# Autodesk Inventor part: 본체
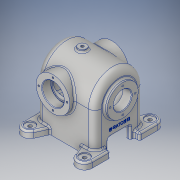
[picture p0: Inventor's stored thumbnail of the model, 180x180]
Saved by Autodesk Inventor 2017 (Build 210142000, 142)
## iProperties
Part Number: 본체
Material: 알루미늄 6061
Document SubType Name: Modeling
Designer: MRC
Density: 2.7 g/cm^3
Appearance: 알루미늄 - 평지
Mass: 1383.94 g
Surface Area: 1150.22 cm^2
Volume: 512.571 cm^3
Author: MRC
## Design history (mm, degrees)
sketch "스케치2"
  geometry: C1 r 45 at (0, 0); 1 further point
  constraints: 1 centre point, 1 coincident
  dimensions: "d0" = 90 diameter of C1
extrude "돌출1" new body sketch "스케치2" distance "d1" = 68; taper "d3" = 0 deg; dims "d2" = 40, "d4" = 0
sketch "스케치3"
  geometry: C1 r 28.5 at (0, 0); 1 further point
  constraints: 1 centre point, 1 coincident
  dimensions: "d5" = 57 diameter of C1
extrude "돌출2" join sketch "스케치3" distance "d6" = 6; taper "d7" = 0 deg
fillet "모깎기1" dims "d8" = 12
sketch "스케치4"
  geometry: C1 r 16.5 at (0, 0); 1 further point
  constraints: 1 centre point, 1 coincident
  dimensions: "d9" = 33 diameter of C1
extrude "돌출3" cut sketch "스케치4" distance "d10" = 16; taper "d11" = 0 deg
sketch "스케치5"
  geometry: C1 r 36 at (0, 0); 1 further point
  constraints: 1 centre point, 1 coincident
  dimensions: "d12" = 72 diameter of C1
extrude "돌출4" cut sketch "스케치5" distance "d13" = 90; taper "d14" = 0 deg
node "작업 평면1"
sketch "스케치11"
  geometry: L1 (28, -45)-(-56, -45); L2 (-68, -33)-(-68, 33); L3 (-56, 45)-(28, 45); L4 (40, 33)-(40, -33); L5 (-56, -36)-(28, -36); L6 (31, -33)-(31, 33); L7 (28, 36)-(-56, 36); L8 (-59, 33)-(-59, -33); A1 r 12 centre (28, -33) between (28, -45) and (40, -33); A2 r 12 centre (-56, -33) between (-68, -33) and (-56, -45); A3 r 12 centre (-56, 33) between (-56, 45) and (-68, 33); A4 r 12 centre (28, 33) between (40, 33) and (28, 45); A5 r 3 centre (28, -33) between (28, -36) and (31, -33); A6 r 3 centre (28, 33) between (31, 33) and (28, 36); A7 r 3 centre (-56, 33) between (-56, 36) and (-59, 33); A8 r 3 centre (-56, -33) between (-59, -33) and (-56, -36); 4 further points
  constraints: 16 end point, 16 point on circle, 8 centre point, 8 tangent, 6 point on line, 4 parallel, 3 equal radius, 2 perpendicular, 1 horizontal, 7 other
  dimensions: "d16" = 90 distance of point (40, 45) point (40, -45); "d17" = 108 distance of point (40, -45) point (-68, -45); "d18" = 40 distance from line of point (0, 0) L4; "d19" = 45 distance from line of point (0, 0) L1; "d20" = 12 radius of A1; "d57" = 9 distance between parallel lines of L1 L5
extrude "돌출5" join sketch "스케치11" stored distance "d21" = 90; taper "d22" = 0 deg
sketch "스케치12"
  geometry: L1 (-20, -99)-(20, -99); L2 (20, -99)-(20, -53); L3 (20, -53)-(-20, -53); L4 (-20, -53)-(-20, -99); L5 (-20, -99)-(20, -53); L6 (20, -99)-(-20, -53); L7 (33, -76)-(-33, -76) reference; 6 further points
  constraints: 12 end point, 6 midpoint, 2 coincident, 2 parallel, 1 horizontal, 1 perpendicular
  dimensions: "d23" = 40 distance of L3.end L2.end; "d24" = 46 distance of L2.end L1.end
extrude "돌출6" cut sketch "스케치12" stored distance "d25" = 90; taper "d26" = 0 deg
sketch "스케치13"
  geometry: A1 r 23 centre (0, 0) between (0, 23) and (23, 0); 3 further points
  constraints: 4 point on circle, 2 horizontal alignment, 2 vertical alignment, 1 centre point, 1 coincident
  dimensions: "d27" = 46 diameter of A1
hole "구멍1" sketch "스케치13" at (0, 23), (23, 0), (0, -23), (-23, 0) diameter "d28" = 3.242; stored, may be unused: countersink angle "d32" = 90 deg, drill point angle "d34" = 118 deg; dims "d29" = 8, "d30" = 4, "d31" = 2, "d33" = 10
node "작업 평면2"
sketch "스케치18"
  geometry: C1 r 31 at (0, 0); 1 further point
  constraints: 1 centre point, 1 coincident
  dimensions: "d40" = 62 diameter of C1
extrude "돌출8" join sketch "스케치18" stored distance "d41" = 90; taper "d42" = 0 deg
sketch "스케치19"
  geometry: L1 (-28, 0)-(56, 0) reference; A1 r 26 centre (0, 0) between (0, 26) and (0, -26); 3 further points
  constraints: 4 point on circle, 2 point on line, 2 vertical alignment, 1 centre point, 1 coincident
  dimensions: "d43" = 52 diameter of A1
hole "구멍2" sketch "스케치19" at (0, 26), (0, -26), (26, 0), (-26, 0) diameter "d44" = 3.242; stored, may be unused: countersink angle "d48" = 90 deg, drill point angle "d50" = 118 deg; dims "d45" = 8, "d46" = 4, "d47" = 2, "d49" = 10
sketch "스케치20"
  geometry: C1 r 20 at (0, 0); 1 further point
  constraints: 1 centre point, 1 coincident
  dimensions: "d51" = 40 diameter of C1
extrude "돌출9" cut sketch "스케치20" distance "d52" = 16; taper "d53" = 0 deg
sketch "스케치21"
  geometry: C1 r 17.5 at (0, 0); 1 further point
  constraints: 1 centre point, 1 coincident
  dimensions: "d54" = 35 diameter of C1
extrude "돌출10" cut sketch "스케치21" stored distance "d55" = 90; taper "d56" = 0 deg
node "작업 평면3"
sketch "스케치22"
  geometry: L1 (-14, -75.6)-(-14, 75.6) reference; L2 (-96.8, 0)-(62.8, 0) reference; L3 (-58, -36)-(32, -36) reference; L4 (-58, -36)-(32, -36) reference; L5 (-58, 36)-(32, 36) reference; L6 (50, 60)-(50, 27); L7 (50, 27)-(31, 27); L8 (31, 20)-(31, 33) reference; L9 (28, 36)-(-56, 36) reference; L10 (9.994, 36)-(14, 45); L11 (31, 27)-(31, 36); L12 (31, 36)-(9.994, 36); L13 (-56, 45)-(28, 45) reference; L14 (14, 45)-(23.21, 65.693); A1 r 14 centre (36, 60) between (50, 60) and (23.21, 65.693); 1 further point
  constraints: 12 end point, 4 point on line, 3 tangent, 2 point on circle, 2 vertical, 1 centre point, 1 collinear, 1 perpendicular
  dimensions: "d58" = 28 diameter of A1; "d59" = 60 distance from line of A1.centre L2; "d60" = 50 distance from line of L1 A1.centre; "d61" = 36 distance from line of L6 L10.end; "d62" = 18 distance between parallel lines of L13 L7
extrude "돌출11" join sketch "스케치22" distance "d63" = 12; taper "d64" = 0 deg
node "작업 평면4"
sketch "스케치24"
  geometry: C1 r 7.5 at (0, 0); 1 further point
  constraints: 1 centre point, 1 coincident
  dimensions: "d66" = 15 diameter of C1
extrude "돌출12" join sketch "스케치24" stored distance "d67" = 12; taper "d68" = 0 deg
sketch "스케치25"
  geometry: 2 further points
  constraints: 1 coincident
hole "구멍3" sketch "스케치25" at (0, 0) diameter "d69" = 5.188; stored, may be unused: countersink angle "d73" = 90 deg, drill point angle "d75" = 118 deg; dims "d70" = 20, "d71" = 4, "d72" = 2, "d74" = 20
sketch "스케치26"
  geometry: A1 r 14 centre (-36, 60) between (-23.21, 65.693) and (-50, 60) reference; A2 r 14 centre (64, 60) between (78, 60) and (51.21, 65.693) reference; A3 r 14 centre (-36, -60) between (-50, -60) and (-23.21, -65.693) reference; A4 r 14 centre (64, -60) between (51.21, -65.693) and (78, -60) reference; 5 further points
  constraints: 4 coincident
hole "구멍4" sketch "스케치26" at (-36, 60), (64, 60), (-36, -60), (64, -60) diameter "d76" = 6.6; stored, may be unused: countersink angle "d80" = 90 deg, drill point angle "d82" = 118 deg; dims "d77" = 20, "d78" = 18, "d79" = 2, "d81" = 12
fillet "모깎기2" dims "d83" = 0.3
fillet "모깎기3" dims "d84" = 3
chamfer "모따기1" distance "d85" = 1; stored, may be unused: second distance "d86" = 2, angle "d87" = 45 deg
fillet "모깎기4" dims "d88" = 3
sketch "스케치27"
  geometry: L1 (30, -76)-(60, -76) reference; 2 further points
  constraints: 1 vertical alignment, 1 other
  dimensions: "d89" = 35 distance from line of point (0, -41) L1
feature "엠보싱1" sketch "스케치27" dims "d90" = 0.5, "d91" = 0
node "솔리드1"
mirror "미러1"
mirror "미러2"
mirror "미러3"
mirror "미러4"
other parameters: "d15" = -76, "d39" = 54, "d65" = 125
